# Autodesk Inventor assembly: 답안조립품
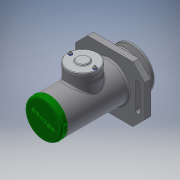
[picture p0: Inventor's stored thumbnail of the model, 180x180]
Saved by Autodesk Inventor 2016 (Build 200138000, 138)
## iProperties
Created: 2017-10
Part Number: 답안조립품
Material: 일반
Document SubType Name: Weldment
Designer: USER
Weld Material: Welded Aluminum-6061
Author: USER
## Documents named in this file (20)
- C:\Users\USER\Desktop\471007V1022\답안조립품.iam
- C:\Users\USER\Desktop\471007V1022\본체.ipt
- C:\Users\USER\Desktop\471007V1022\V-벨트풀리.ipt
- C:\Users\USER\Desktop\471007V1022\너트 M10.ipt
- C:\Users\USER\Desktop\471007V1022\멈춤링 15 x 1.ipt
- C:\Users\USER\Desktop\471007V1022\멈춤링 35x1.6.ipt
- C:\Users\USER\Desktop\471007V1022\베어링 15 x 35 x 11.ipt
- C:\Users\USER\Desktop\471007V1022\볼트 M4 x 10.ipt
- C:\Users\USER\Desktop\471007V1022\부시1.ipt
- C:\Users\USER\Desktop\471007V1022\부시2.ipt
- C:\Users\USER\Desktop\471007V1022\사이드 커버.ipt
- 사이드 커버.ipt
- C:\Users\USER\Desktop\471007V1022\십자볼트 M3 x 10.ipt
- C:\Users\USER\Desktop\471007V1022\오일 실 15 25 7.ipt
- C:\Users\USER\Desktop\471007V1022\와셔 3x6.ipt
- C:\Users\USER\Desktop\471007V1022\와셔 4x16.ipt
- C:\Users\USER\Desktop\471007V1022\와셔 10x21.ipt
- C:\Users\USER\Desktop\471007V1022\축.ipt
- C:\Users\USER\Desktop\471007V1022\키 4 x 4 x 18.ipt
- C:\Users\USER\Desktop\471007V1022\탑 커버.ipt
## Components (2 placed, 2 different names)
1. V-벨트풀리:1
2. ISO 4017 M4 x 10:1
